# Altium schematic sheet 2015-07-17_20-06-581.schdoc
size 300 x 170 mm; SheetNumber: 1; SheetTotal: 1
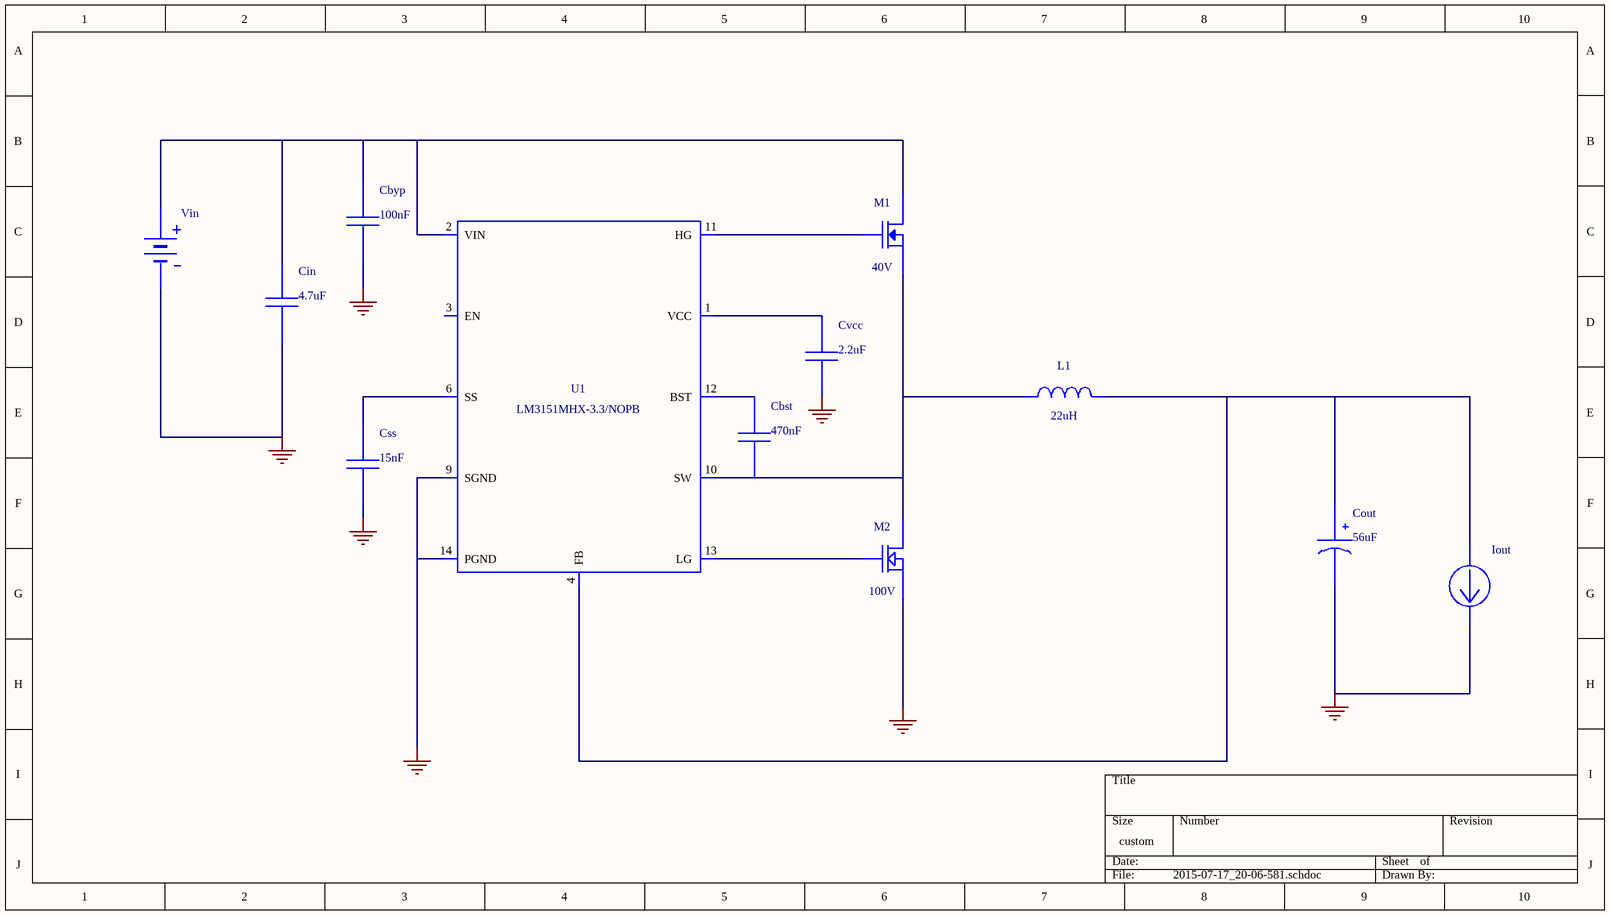
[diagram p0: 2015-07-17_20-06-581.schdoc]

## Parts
Cbst  value 470nF  (hidden comment: EMK212B7474KD-T)
Cbyp  value 100nF  (hidden comment: C0805C104K5RACTU)
Cin  value 4.7uF  (hidden comment: GRM31CR71H475KA12L)
Cout  value 56uF  (hidden comment: 10SVP56M)
Css  value 15nF  (hidden comment: CC0805KRX7R9BB153)
Cvcc  value 2.2uF  (hidden comment: EMK212B7225KG-T)
Iout  WB_CURRENT_LOAD  (value not drawn)
L1  value 22uH  (hidden comment: SER2915L-223KL)
M1  value 40V  (hidden comment: SI4446DY)
M2  value 100V  (hidden comment: BSC265N10LSF G)
U1  LM3151MHX-3.3/NOPB
Vin  WB_BATTERY  (value not drawn)

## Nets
0: Cbyp.2 Cin.2 Cout.2(-) Css.2 Cvcc.2 Iout.2(-) M2.1(Source) M2.2(Source) M2.3(Source) U1.5(SGND) U1.7(PGND) U1.8(PGND) U1.9(SGND) U1.14(PGND) U1.15(DAP) Vin.2(-)
NetCbst_1: Cbst.1 U1.12(BST)
NetCbst_2: Cbst.2 L1.1 M1.1(Source) M1.2(Source) M1.3(Source) M2.5(Drain) M2.6(Drain) M2.7(Drain) M2.8(Drain) M2.9(Drain) U1.10(SW)
NetCbyp_1: Cbyp.1 Cin.1 M1.5(Drain) M1.6(Drain) M1.7(Drain) M1.8(Drain) U1.2(VIN) Vin.1(+)
NetCout_1: Cout.1(+) Iout.1(+) L1.2 U1.4(FB)
NetCss_1: Css.1 U1.6(SS)
NetCvcc_1: Cvcc.1 U1.1(VCC)
NetM1_4: M1.4(Gate) U1.11(HG)
NetM2_4: M2.4(Gate) U1.13(LG)

Not connected (* = marked no-connect by the designer): U1 3(EN)

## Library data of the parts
Cbst = EMK212B7474KD-T: Manufacturer Name: Taiyo Yuden
Cbyp = C0805C104K5RACTU: Manufacturer Name: Kemet
Cin = GRM31CR71H475KA12L: GRM31CR71H475KA1; Manufacturer Name: MuRata
Cout = 10SVP56M: Manufacturer Name: Panasonic
Css = CC0805KRX7R9BB153: CC0805KRX7R9BB15; Manufacturer Name: Yageo America
Cvcc = EMK212B7225KG-T: Manufacturer Name: Taiyo Yuden
Iout = WB_CURRENT_LOAD: Value: UNLISTED
L1 = SER2915L-223KL: Manufacturer Name: Coilcraft
M1 = SI4446DY: Manufacturer Name: Vishay-Siliconix
M2 = BSC265N10LSF G: Manufacturer Name: Infineon Technologies
U1 = LM3151MHX-3.3/NOPB: LM3151MHX-3.3/NO; Manufacturer Name: Texas Instruments; Value: UNLISTED
Vin = WB_BATTERY: Value: UNLISTED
